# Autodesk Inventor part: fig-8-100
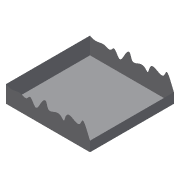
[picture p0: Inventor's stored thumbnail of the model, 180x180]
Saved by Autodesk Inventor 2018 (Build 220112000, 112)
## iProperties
Shininess: 64.0
Length Units: 11269
Angle Units: 11279
Time Units: 11290
Mass Units: 11283
Length Display Precision: 3
Angle Display Precision: 2
Compacted: True
Part Number: fig-8-100
Document SubType Name: Modeling
Created: 2002-12
Designer: deepak
Density: 1 g/cm^3
Material: Generic
Surface Area: 62.5725 cm^2
Appearance: Default
Density: 0.0
Volumn: 0.0
Area: 0.0
PropertySet Name: Model Information
Control State: 0
Master: False
Checked Out: False
Author: deepak
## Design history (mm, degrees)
sketch "Sketch1"
  geometry: L1 (-32.188, 30.089)-(27.812, 30.089); L2 (27.812, 30.089)-(27.812, -29.911); L3 (27.812, -29.911)-(-32.188, -29.911); L4 (-32.188, -29.911)-(-32.188, 30.089)
  constraints: 8 end point, 2 parallel, 1 horizontal, 1 perpendicular
  dimensions: "d0" = 60 distance of L1.start L1.end; "d1" = 60 distance of L3.end L1.start
extrude "Extrusion1" new body sketch "Sketch1" stored distance "d2" = 20; taper "d3" = 0 deg
sketch "Sketch2"
  geometry: 17 further points
  constraints: 17 other
extrude_surface "ExtrusionSrf1" sketch "Sketch2" dims "d4" = 70, "d5" = 0
split "Split1"
delete_face "Delete Face2"
body "Solid1"
body "Srf1"
